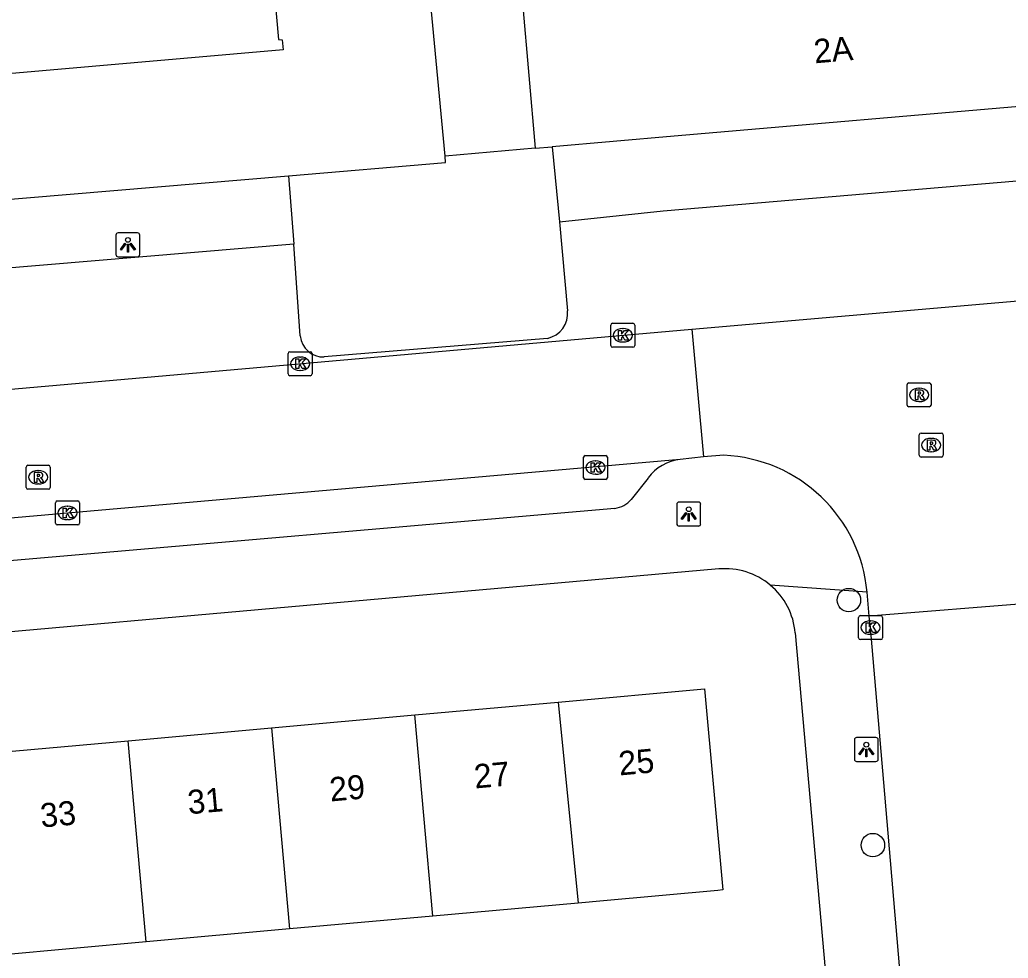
# Model space of a CAD drawing. Extents: x 160557 to 161245, y 385330 to 386505.
# Drawn here: x 160953.15 to 160994.37, y 385596.86 to 385636 of the extents above; entities that cross this region are included whole.
import ezdxf

# ---------------------------------------------------------------- set-up
doc = ezdxf.new("R2010")
doc.units = 0
for name, color, linetype in [('IMGEO_Boom', 7, 'Continuous'), ('IMGEO_Erf', 7, 'Continuous'), ('IMGEO_Kolk', 7, 'Continuous'), ('IMGEO_Lichtpunt', 7, 'Continuous'), ('IMGEO_Pand', 7, 'Continuous'), ('IMGEO_Pand_nummerreeks', 7, 'Continuous'), ('IMGEO_Rijbaan_lokaal_open', 7, 'Continuous'), ('IMGEO_Rioolput', 7, 'Continuous'), ('IMGEO_Voetpad_open', 7, 'Continuous')]:
    doc.layers.add(name, color=color, linetype=linetype)

msp = doc.modelspace()

# ---------------------------------------------------------------- linework, layer by layer
at = {"layer": 'IMGEO_Boom'}
for centre in [(160987.728, 385611.799), (160988.729, 385601.58)]:
    msp.add_circle(centre, 0.489, dxfattribs=at)
at = {"layer": 'IMGEO_Erf'}
msp.add_lwpolyline([(160970.885, 385630.314), (160968.714, 385653.444)], dxfattribs=at)
at = {"layer": 'IMGEO_Kolk'}
for p, q in [((160977.797, 385622.414), (160977.797, 385623.266)), ((160977.872, 385623.34), (160978.724, 385623.34)), ((160978.285, 385623.12), (160978.31, 385623.12)), ((160978.798, 385623.266), (160978.798, 385622.414)), ((160978.724, 385622.34), (160977.872, 385622.34)), ((160978.308, 385622.56), (160978.283, 385622.56)), ((160964.341, 385621.228), (160964.341, 385622.08)), ((160964.416, 385622.154), (160965.268, 385622.154)), ((160964.829, 385621.934), (160964.854, 385621.934)), ((160965.342, 385622.08), (160965.342, 385621.228)), ((160964.852, 385621.374), (160964.827, 385621.374)), ((160965.268, 385621.154), (160964.416, 385621.154)), ((160976.661, 385616.9), (160976.661, 385617.752)), ((160976.736, 385617.826), (160977.588, 385617.826)), ((160977.662, 385617.752), (160977.662, 385616.9)), ((160977.149, 385617.606), (160977.174, 385617.606)), ((160977.588, 385616.826), (160976.736, 385616.826)), ((160977.172, 385617.046), (160977.147, 385617.046)), ((160954.642, 385615.007), (160954.642, 385615.859)), ((160954.717, 385615.933), (160955.569, 385615.933)), ((160955.13, 385615.713), (160955.155, 385615.713)), ((160955.643, 385615.859), (160955.643, 385615.007)), ((160955.569, 385614.933), (160954.717, 385614.933)), ((160955.153, 385615.153), (160955.128, 385615.153)), ((160988.131, 385610.225), (160988.131, 385611.077)), ((160988.206, 385611.151), (160989.058, 385611.151)), ((160989.132, 385611.077), (160989.132, 385610.225)), ((160988.619, 385610.931), (160988.644, 385610.931)), ((160988.642, 385610.371), (160988.617, 385610.371)), ((160989.058, 385610.151), (160988.206, 385610.151))]:
    msp.add_line(p, q, dxfattribs=at)
for points in [[(160977.797, 385622.414), (160977.797, 385623.266)], [(160977.872, 385623.34), (160978.724, 385623.34)], [(160978.118, 385623.04), (160978.241, 385623.04), (160978.241, 385622.889), (160978.371, 385623.04), (160978.535, 385623.04), (160978.389, 385622.889), (160978.542, 385622.64), (160978.39, 385622.64), (160978.305, 385622.804), (160978.241, 385622.737), (160978.241, 385622.64), (160978.118, 385622.64), (160978.118, 385623.04)], [(160978.798, 385623.266), (160978.798, 385622.414)], [(160978.724, 385622.34), (160977.872, 385622.34)], [(160964.341, 385621.228), (160964.341, 385622.08)], [(160964.416, 385622.154), (160965.268, 385622.154)], [(160964.662, 385621.854), (160964.785, 385621.854), (160964.785, 385621.703), (160964.915, 385621.854), (160965.079, 385621.854), (160964.933, 385621.703), (160965.086, 385621.454), (160964.934, 385621.454), (160964.849, 385621.618), (160964.785, 385621.551), (160964.785, 385621.454), (160964.662, 385621.454), (160964.662, 385621.854)], [(160965.342, 385622.08), (160965.342, 385621.228)], [(160965.268, 385621.154), (160964.416, 385621.154)], [(160976.661, 385616.9), (160976.661, 385617.752)], [(160976.736, 385617.826), (160977.588, 385617.826)], [(160977.662, 385617.752), (160977.662, 385616.9)], [(160976.982, 385617.526), (160977.105, 385617.526), (160977.105, 385617.375), (160977.235, 385617.526), (160977.399, 385617.526), (160977.253, 385617.375), (160977.406, 385617.126), (160977.254, 385617.126), (160977.169, 385617.29), (160977.105, 385617.223), (160977.105, 385617.126), (160976.982, 385617.126), (160976.982, 385617.526)], [(160977.588, 385616.826), (160976.736, 385616.826)], [(160954.642, 385615.007), (160954.642, 385615.859)], [(160954.717, 385615.933), (160955.569, 385615.933)], [(160954.963, 385615.633), (160955.086, 385615.633), (160955.086, 385615.482), (160955.216, 385615.633), (160955.38, 385615.633), (160955.234, 385615.482), (160955.387, 385615.233), (160955.235, 385615.233), (160955.15, 385615.397), (160955.086, 385615.33), (160955.086, 385615.233), (160954.963, 385615.233), (160954.963, 385615.633)], [(160955.643, 385615.859), (160955.643, 385615.007)], [(160955.569, 385614.933), (160954.717, 385614.933)], [(160988.131, 385610.225), (160988.131, 385611.077)], [(160988.206, 385611.151), (160989.058, 385611.151)], [(160989.132, 385611.077), (160989.132, 385610.225)], [(160988.452, 385610.851), (160988.575, 385610.851), (160988.575, 385610.7), (160988.705, 385610.851), (160988.869, 385610.851), (160988.723, 385610.7), (160988.876, 385610.451), (160988.724, 385610.451), (160988.639, 385610.615), (160988.575, 385610.548), (160988.575, 385610.451), (160988.452, 385610.451), (160988.452, 385610.851)], [(160989.058, 385610.151), (160988.206, 385610.151)]]:
    msp.add_lwpolyline(points, dxfattribs=at)
for centre, start, end in [((160977.874, 385623.264), 91.552, 178.448), ((160977.874, 385623.264), 91.552, 178.448), ((160978.722, 385623.264), 1.552, 88.448), ((160978.722, 385623.264), 1.552, 88.448), ((160977.874, 385622.416), 181.552, 268.448), ((160977.874, 385622.416), 181.552, 268.448), ((160978.722, 385622.416), 271.552, 358.448), ((160978.722, 385622.416), 271.552, 358.448), ((160964.418, 385622.078), 91.552, 178.448), ((160964.418, 385622.078), 91.552, 178.448), ((160965.266, 385622.078), 1.552, 88.448), ((160965.266, 385622.078), 1.552, 88.448), ((160964.418, 385621.23), 181.552, 268.448), ((160964.418, 385621.23), 181.552, 268.448), ((160965.266, 385621.23), 271.552, 358.448), ((160965.266, 385621.23), 271.552, 358.448), ((160976.738, 385617.75), 91.552, 178.448), ((160976.738, 385617.75), 91.552, 178.448), ((160977.586, 385617.75), 1.552, 88.448), ((160977.586, 385617.75), 1.552, 88.448), ((160976.738, 385616.902), 181.552, 268.448), ((160976.738, 385616.902), 181.552, 268.448), ((160977.586, 385616.902), 271.552, 358.448), ((160977.586, 385616.902), 271.552, 358.448), ((160954.719, 385615.857), 91.552, 178.448), ((160954.719, 385615.857), 91.552, 178.448), ((160955.567, 385615.857), 1.552, 88.448), ((160955.567, 385615.857), 1.552, 88.448), ((160954.719, 385615.009), 181.552, 268.448), ((160954.719, 385615.009), 181.552, 268.448), ((160955.567, 385615.009), 271.552, 358.448), ((160955.567, 385615.009), 271.552, 358.448), ((160988.208, 385611.075), 91.552, 178.448), ((160988.208, 385611.075), 91.552, 178.448), ((160989.056, 385611.075), 1.552, 88.448), ((160989.056, 385611.075), 1.552, 88.448), ((160988.208, 385610.227), 181.552, 268.448), ((160988.208, 385610.227), 181.552, 268.448), ((160989.056, 385610.227), 271.552, 358.448), ((160989.056, 385610.227), 271.552, 358.448)]:
    msp.add_arc(centre, 0.0765, start, end, dxfattribs=at)
for centre, major_axis, ratio, start_param, end_param in [((160978.284, 385622.84), (-0.387, 0.002), 0.722429, 4.712389, 7.853982), ((160978.309, 385622.84), (-0.39, 0.002), 0.717154, 1.570796, 4.712389), ((160964.828, 385621.654), (-0.387, 0.002), 0.722429, 4.712389, 7.853982), ((160964.853, 385621.654), (-0.39, 0.002), 0.717154, 1.570796, 4.712389), ((160977.148, 385617.326), (-0.387, 0.002), 0.722429, 4.712389, 7.853982), ((160977.173, 385617.326), (-0.39, 0.002), 0.717154, 1.570796, 4.712389), ((160955.129, 385615.433), (-0.387, 0.002), 0.722429, 4.712389, 7.853982), ((160955.154, 385615.433), (-0.39, 0.002), 0.717154, 1.570796, 4.712389), ((160988.618, 385610.651), (-0.387, 0.002), 0.722429, 4.712389, 7.853982), ((160988.643, 385610.651), (-0.39, 0.002), 0.717154, 1.570796, 4.712389)]:
    msp.add_ellipse(centre, major_axis=major_axis, ratio=ratio, start_param=start_param, end_param=end_param, dxfattribs=at)
at = {"layer": 'IMGEO_Lichtpunt'}
for p, q in [((160958.063, 385627.113), (160957.255, 385627.113)), ((160958.063, 385627.113), (160957.255, 385627.113)), ((160957.161, 385627.018), (160957.161, 385626.211)), ((160957.161, 385627.018), (160957.161, 385626.211)), ((160958.157, 385626.211), (160958.157, 385627.018)), ((160958.157, 385626.211), (160958.157, 385627.018)), ((160957.255, 385626.117), (160958.063, 385626.117)), ((160957.255, 385626.117), (160958.063, 385626.117)), ((160980.551, 385615.789), (160980.551, 385614.982)), ((160980.551, 385615.789), (160980.551, 385614.982)), ((160981.453, 385615.884), (160980.645, 385615.884)), ((160981.453, 385615.884), (160980.645, 385615.884)), ((160981.547, 385614.982), (160981.547, 385615.789)), ((160981.547, 385614.982), (160981.547, 385615.789)), ((160980.645, 385614.888), (160981.453, 385614.888)), ((160980.645, 385614.888), (160981.453, 385614.888)), ((160987.957, 385605.971), (160987.957, 385605.164)), ((160987.957, 385605.971), (160987.957, 385605.164)), ((160988.859, 385606.066), (160988.051, 385606.066)), ((160988.859, 385606.066), (160988.051, 385606.066)), ((160988.953, 385605.164), (160988.953, 385605.971)), ((160988.953, 385605.164), (160988.953, 385605.971)), ((160988.051, 385605.07), (160988.859, 385605.07)), ((160988.051, 385605.07), (160988.859, 385605.07))]:
    msp.add_line(p, q, dxfattribs=at)
for points in [[(160957.535, 385626.682), (160957.574, 385626.654), (160957.386, 385626.392), (160957.348, 385626.419), (160957.535, 385626.682)], [(160957.637, 385626.634), (160957.684, 385626.634), (160957.684, 385626.312), (160957.637, 385626.312), (160957.637, 385626.634)], [(160957.747, 385626.654), (160957.785, 385626.681), (160957.972, 385626.419), (160957.933, 385626.391), (160957.747, 385626.654)], [(160980.925, 385615.453), (160980.964, 385615.425), (160980.776, 385615.163), (160980.738, 385615.19), (160980.925, 385615.453)], [(160981.027, 385615.405), (160981.074, 385615.405), (160981.074, 385615.083), (160981.027, 385615.083), (160981.027, 385615.405)], [(160981.137, 385615.425), (160981.175, 385615.452), (160981.362, 385615.19), (160981.323, 385615.162), (160981.137, 385615.425)], [(160988.331, 385605.635), (160988.37, 385605.607), (160988.182, 385605.345), (160988.144, 385605.372), (160988.331, 385605.635)], [(160988.433, 385605.587), (160988.48, 385605.587), (160988.48, 385605.265), (160988.433, 385605.265), (160988.433, 385605.587)], [(160988.543, 385605.607), (160988.581, 385605.634), (160988.768, 385605.372), (160988.729, 385605.344), (160988.543, 385605.607)]]:
    msp.add_lwpolyline(points, dxfattribs=at)
for centre in [(160957.66, 385626.816), (160981.05, 385615.587), (160988.456, 385605.769)]:
    msp.add_circle(centre, 0.0994, dxfattribs=at)
for centre, start, end in [((160957.255, 385627.018), 90, 180), ((160957.255, 385627.018), 90, 180), ((160958.063, 385627.018), 0, 90), ((160958.063, 385627.018), 0, 90), ((160957.255, 385626.211), 180, 270), ((160957.255, 385626.211), 180, 270), ((160958.063, 385626.211), 270, 0), ((160958.063, 385626.211), 270, 360), ((160980.645, 385615.789), 90, 180), ((160980.645, 385615.789), 90, 180), ((160981.453, 385615.789), 0, 90), ((160981.453, 385615.789), 0, 90), ((160980.645, 385614.982), 180, 270), ((160980.645, 385614.982), 180, 270), ((160981.453, 385614.982), 270, 0), ((160981.453, 385614.982), 270, 360), ((160988.051, 385605.971), 90, 180), ((160988.051, 385605.971), 90, 180), ((160988.859, 385605.971), 0, 90), ((160988.859, 385605.971), 0, 90), ((160988.051, 385605.164), 180, 270), ((160988.051, 385605.164), 180, 270), ((160988.859, 385605.164), 270, 0), ((160988.859, 385605.164), 270, 360)]:
    msp.add_arc(centre, 0.0946, start, end, dxfattribs=at)
at = {"layer": 'IMGEO_Pand'}
for points in [[(160968.714, 385653.444), (160968.005, 385653.367), (160968.951, 385642.66), (160963.319, 385642.172), (160963.939, 385635.17), (160964.1, 385635.164), (160964.134, 385634.743), (160949.94, 385633.511), (160949.904, 385633.932), (160950.055, 385633.931), (160949.455, 385640.834), (160949.443, 385640.975), (160942.91, 385640.389), (160941.064, 385633.675), (160941.217, 385633.639), (160941.099, 385633.233), (160933.113, 385635.47), (160934.444, 385640.29), (160938.817, 385656.14), (160938.325, 385656.372)], [(160979.998, 385637.202), (160974.123, 385636.696), (160974.644, 385630.643)], [(160995.973, 385632.481), (160980.444, 385631.143), (160975.35, 385630.704)], [(160974.644, 385630.643), (160975.35, 385630.704)], [(160975.6, 385607.546), (160981.711, 385608.096), (160982.467, 385599.711), (160982.261, 385599.692), (160977.488, 385599.262), (160976.436, 385599.167)], [(160969.625, 385607.008), (160975.6, 385607.546)], [(160975.6, 385607.546), (160976.436, 385599.167)], [(160963.649, 385606.469), (160969.625, 385607.008)], [(160970.38, 385598.622), (160969.625, 385607.008)], [(160957.673, 385605.931), (160963.649, 385606.469)], [(160963.649, 385606.469), (160964.404, 385598.084)], [(160958.428, 385597.545), (160952.319, 385596.995), (160952.012, 385600.402), (160951.564, 385605.381), (160957.673, 385605.931)], [(160958.428, 385597.545), (160957.673, 385605.931)], [(160976.436, 385599.167), (160970.38, 385598.622)], [(160970.38, 385598.622), (160964.404, 385598.084)], [(160964.404, 385598.084), (160958.428, 385597.545)]]:
    msp.add_lwpolyline(points, dxfattribs=at)
at = {"layer": 'IMGEO_Rijbaan_lokaal_open'}
for points in [[(160981.174, 385623.093), (161000.539, 385624.784)], [(160926.97, 385618.393), (160943.788, 385619.799), (160981.174, 385623.093)], [(160981.174, 385623.093), (160981.664, 385617.775)], [(160980.691, 385617.662), (160948.787, 385614.873)], [(160981.664, 385617.775), (160980.691, 385617.662)], [(160982.513, 385617.839), (160981.664, 385617.775)], [(160988.57, 385611.128), (160988.486, 385612.123)], [(160995.517, 385611.683), (160988.57, 385611.128)], [(160990.456, 385589.389), (160989.182, 385604.198), (160988.633, 385610.652), (160988.57, 385611.128)]]:
    msp.add_lwpolyline(points, dxfattribs=at)
msp.add_arc((160982.232, 385611.567), 6.278, 5.0818, 87.4372, dxfattribs=at)
at = {"layer": 'IMGEO_Rioolput'}
for p, q in [((160990.155, 385619.93), (160990.155, 385620.782)), ((160990.23, 385620.856), (160991.082, 385620.856)), ((160990.643, 385620.636), (160990.668, 385620.636)), ((160991.156, 385620.782), (160991.156, 385619.93)), ((160991.082, 385619.856), (160990.23, 385619.856)), ((160990.666, 385620.076), (160990.641, 385620.076)), ((160990.662, 385617.835), (160990.662, 385618.687)), ((160990.737, 385618.761), (160991.589, 385618.761)), ((160991.15, 385618.541), (160991.175, 385618.541)), ((160991.663, 385618.687), (160991.663, 385617.835)), ((160991.589, 385617.761), (160990.737, 385617.761)), ((160991.173, 385617.981), (160991.148, 385617.981)), ((160953.419, 385616.495), (160953.419, 385617.347)), ((160953.494, 385617.421), (160954.346, 385617.421)), ((160954.42, 385617.347), (160954.42, 385616.495)), ((160953.907, 385617.201), (160953.932, 385617.201)), ((160954.346, 385616.421), (160953.494, 385616.421)), ((160953.93, 385616.641), (160953.905, 385616.641))]:
    msp.add_line(p, q, dxfattribs=at)
for points in [[(160990.155, 385619.93), (160990.155, 385620.782)], [(160990.23, 385620.856), (160991.082, 385620.856)], [(160990.744, 385620.554), (160990.492, 385620.556), (160990.492, 385620.156)], [(160991.156, 385620.782), (160991.156, 385619.93)], [(160990.492, 385620.156), (160990.616, 385620.156), (160990.616, 385620.318), (160990.627, 385620.318)], [(160990.67, 385620.475), (160990.616, 385620.475), (160990.616, 385620.394)], [(160990.616, 385620.394), (160990.668, 385620.394)], [(160990.674, 385620.289), (160990.745, 385620.156), (160990.885, 385620.156), (160990.82, 385620.282)], [(160991.082, 385619.856), (160990.23, 385619.856)], [(160990.662, 385617.835), (160990.662, 385618.687)], [(160990.737, 385618.761), (160991.589, 385618.761)], [(160991.251, 385618.459), (160990.999, 385618.461), (160990.999, 385618.061)], [(160991.663, 385618.687), (160991.663, 385617.835)], [(160990.999, 385618.061), (160991.123, 385618.061), (160991.123, 385618.223), (160991.134, 385618.223)], [(160991.177, 385618.38), (160991.123, 385618.38), (160991.123, 385618.299)], [(160991.123, 385618.299), (160991.175, 385618.299)], [(160991.181, 385618.194), (160991.252, 385618.061), (160991.392, 385618.061), (160991.327, 385618.187)], [(160991.589, 385617.761), (160990.737, 385617.761)], [(160953.419, 385616.495), (160953.419, 385617.347)], [(160953.494, 385617.421), (160954.346, 385617.421)], [(160954.42, 385617.347), (160954.42, 385616.495)], [(160954.008, 385617.119), (160953.756, 385617.121), (160953.756, 385616.721)], [(160953.756, 385616.721), (160953.88, 385616.721), (160953.88, 385616.883), (160953.891, 385616.883)], [(160953.934, 385617.04), (160953.88, 385617.04), (160953.88, 385616.959)], [(160953.88, 385616.959), (160953.932, 385616.959)], [(160953.938, 385616.854), (160954.009, 385616.721), (160954.149, 385616.721), (160954.084, 385616.847)], [(160954.346, 385616.421), (160953.494, 385616.421)]]:
    msp.add_lwpolyline(points, dxfattribs=at)
for centre, radius, start, end in [((160990.232, 385620.78), 0.0765, 91.552, 178.448), ((160990.232, 385620.78), 0.0765, 91.552, 178.448), ((160990.743, 385620.444), 0.109, 350.3612, 89.416), ((160991.08, 385620.78), 0.0765, 1.552, 88.448), ((160991.08, 385620.78), 0.0765, 1.552, 88.448), ((160990.626, 385620.265), 0.0533, 26.0293, 88.6989), ((160990.652, 385620.583), 0.19, 274.7715, 282.9687), ((160990.676, 385620.379), 0.0964, 77.0061, 93.1865), ((160990.69, 385620.436), 0.0378, 276.6634, 79.6772), ((160990.741, 385620.444), 0.112, 277.5842, 350.9817), ((160990.725, 385620.229), 0.108, 29.5134, 73.7905), ((160990.232, 385619.932), 0.0765, 181.552, 268.448), ((160990.232, 385619.932), 0.0765, 181.552, 268.448), ((160991.08, 385619.932), 0.0765, 271.552, 358.448), ((160991.08, 385619.932), 0.0765, 271.552, 358.448), ((160990.739, 385618.685), 0.0765, 91.552, 178.448), ((160990.739, 385618.685), 0.0765, 91.552, 178.448), ((160991.25, 385618.349), 0.109, 350.3612, 89.416), ((160991.587, 385618.685), 0.0765, 1.552, 88.448), ((160991.587, 385618.685), 0.0765, 1.552, 88.448), ((160991.133, 385618.17), 0.0533, 26.0293, 88.6989), ((160991.159, 385618.488), 0.19, 274.7715, 282.9687), ((160991.183, 385618.284), 0.0964, 77.0061, 93.1865), ((160991.197, 385618.341), 0.0378, 276.6634, 79.6772), ((160991.248, 385618.349), 0.112, 277.5842, 350.9817), ((160991.232, 385618.134), 0.108, 29.5134, 73.7905), ((160990.739, 385617.837), 0.0765, 181.552, 268.448), ((160990.739, 385617.837), 0.0765, 181.552, 268.448), ((160991.587, 385617.837), 0.0765, 271.552, 358.448), ((160991.587, 385617.837), 0.0765, 271.552, 358.448), ((160953.496, 385617.345), 0.0765, 91.552, 178.448), ((160953.496, 385617.345), 0.0765, 91.552, 178.448), ((160954.344, 385617.345), 0.0765, 1.552, 88.448), ((160954.344, 385617.345), 0.0765, 1.552, 88.448), ((160953.89, 385616.83), 0.0533, 26.0293, 88.6989), ((160953.916, 385617.148), 0.19, 274.7715, 282.9687), ((160953.94, 385616.944), 0.0964, 77.0061, 93.1865), ((160953.954, 385617.001), 0.0378, 276.6634, 79.6772), ((160954.007, 385617.009), 0.109, 350.3612, 89.416), ((160954.005, 385617.009), 0.112, 277.5842, 350.9817), ((160953.989, 385616.794), 0.108, 29.5134, 73.7905), ((160953.496, 385616.497), 0.0765, 181.552, 268.448), ((160953.496, 385616.497), 0.0765, 181.552, 268.448), ((160954.344, 385616.497), 0.0765, 271.552, 358.448), ((160954.344, 385616.497), 0.0765, 271.552, 358.448)]:
    msp.add_arc(centre, radius, start, end, dxfattribs=at)
for centre, major_axis, ratio, start_param, end_param in [((160990.642, 385620.356), (-0.387, 0.002), 0.722429, 4.712389, 7.853982), ((160990.667, 385620.356), (-0.39, 0.002), 0.717154, 1.570796, 4.712389), ((160991.149, 385618.261), (-0.387, 0.002), 0.722429, 4.712389, 7.853982), ((160991.174, 385618.261), (-0.39, 0.002), 0.717154, 1.570796, 4.712389), ((160953.906, 385616.921), (-0.387, 0.002), 0.722429, 4.712389, 7.853982), ((160953.931, 385616.921), (-0.39, 0.002), 0.717154, 1.570796, 4.712389)]:
    msp.add_ellipse(centre, major_axis=major_axis, ratio=ratio, start_param=start_param, end_param=end_param, dxfattribs=at)
at = {"layer": 'IMGEO_Voetpad_open'}
for points in [[(160974.644, 385630.643), (160970.885, 385630.314)], [(160975.35, 385630.704), (160975.666, 385627.571)], [(160964.361, 385629.49), (160970.911, 385630.041), (160970.885, 385630.314)], [(160975.666, 385627.571), (160979.99, 385628.028), (160998.662, 385629.62)], [(160949.779, 385628.263), (160964.361, 385629.49)], [(160964.361, 385629.49), (160964.586, 385626.634)], [(160975.666, 385627.571), (160975.997, 385623.859)], [(160964.586, 385626.634), (160949.978, 385625.415)], [(160964.848, 385622.812), (160964.586, 385626.634)], [(160975.155, 385622.711), (160965.846, 385621.936)], [(160979.359, 385616.889), (160978.649, 385615.999)], [(160977.97, 385615.623), (160951.922, 385613.36)], [(160982.303, 385613.096), (160949.179, 385610.154)], [(160988.486, 385612.123), (160984.45, 385612.422)], [(160985.493, 385610.427), (160987.439, 385588.591), (160987.689, 385585.785), (160987.694, 385585.726)]]:
    msp.add_lwpolyline(points, dxfattribs=at)
for centre, radius, start, end in [((160974.93, 385623.759), 1.072, 282.1402, 5.3435), ((160965.812, 385622.903), 0.968, 185.419, 272.0306), ((160980.899, 385615.77), 1.904, 96.2697, 143.9861), ((160977.829, 385616.679), 1.066, 277.6161, 320.3353), ((160982.56, 385610.159), 2.948, 50.137, 95.0061), ((160982.563, 385610.165), 2.942, 5.1041, 50.0977)]:
    msp.add_arc(centre, radius, start, end, dxfattribs=at)

# ---------------------------------------------------------------- texts
at = {"layer": 'IMGEO_Pand_nummerreeks'}
for s, rotation, p in [('2A', 4.9252, (160986.305, 385634.178)), ('25', 5.1461, (160978.167, 385604.484)), ('27', 5.1461, (160972.138, 385603.941)), ('29', 5.1461, (160966.109, 385603.398)), ('31', 5.1461, (160960.191, 385602.865)), ('33', 5.1461, (160954.05, 385602.312))]:
    msp.add_text(s, height=1, rotation=rotation, dxfattribs=at).set_placement(p)

doc.saveas('drawing.dxf')
